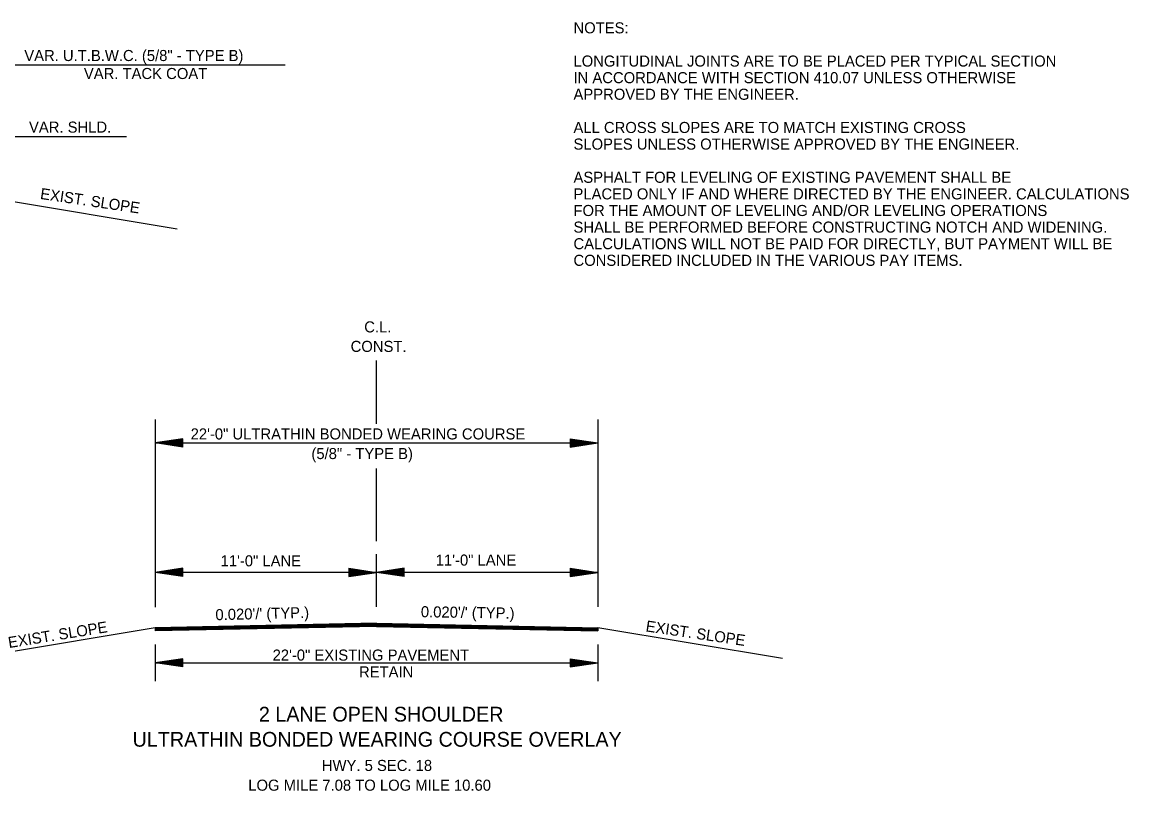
# Model space of a CAD drawing. Extents: x 2263886 to 2266026, y -3122850 to -3121850.
# Drawn here: x 2265457.8 to 2265517.8, y -3122646.9 to -3122605.2 of the extents above; entities that cross this region are included whole.
import ezdxf

# ---------------------------------------------------------------- set-up
doc = ezdxf.new("R2010")
doc.units = 0
doc.layers.add('Default', color=7, linetype='Continuous')
doc.layers.add('R_Border Prem', color=7, linetype='Continuous')

msp = doc.modelspace()

# ---------------------------------------------------------------- linework, layer by layer
at = {"layer": 'R_Border Prem'}
for p, q in [((2265472.094, -3122607.527), (2265448.881, -3122607.527)), ((2265463.497, -3122611.414), (2265452.189, -3122611.414)), ((2265466.233, -3122616.414), (2265456.226, -3122614.746)), ((2265477.045, -3122626.982), (2265477.045, -3122623.539)), ((2265465.045, -3122626.734), (2265465.045, -3122636.907)), ((2265466.545, -3122627.784), (2265465.045, -3122628.009)), ((2265465.045, -3122628.009), (2265489.037, -3122628.009)), ((2265466.545, -3122628.234), (2265465.045, -3122628.009)), ((2265466.545, -3122627.822), (2265465.295, -3122628.009)), ((2265466.545, -3122628.197), (2265465.295, -3122628.009)), ((2265466.545, -3122627.86), (2265465.553, -3122628.009)), ((2265466.545, -3122628.159), (2265465.553, -3122628.009)), ((2265466.545, -3122627.898), (2265465.803, -3122628.009)), ((2265466.545, -3122628.121), (2265465.803, -3122628.009)), ((2265466.545, -3122627.936), (2265466.057, -3122628.009)), ((2265466.545, -3122628.082), (2265466.057, -3122628.009)), ((2265466.545, -3122627.974), (2265466.308, -3122628.009)), ((2265466.545, -3122628.045), (2265466.308, -3122628.009)), ((2265466.545, -3122628.234), (2265466.545, -3122627.784)), ((2265487.537, -3122627.784), (2265489.037, -3122628.009)), ((2265487.537, -3122627.784), (2265487.537, -3122628.234)), ((2265487.537, -3122627.822), (2265488.787, -3122628.009)), ((2265487.537, -3122627.86), (2265488.529, -3122628.009)), ((2265487.537, -3122627.898), (2265488.279, -3122628.009)), ((2265487.537, -3122627.937), (2265488.025, -3122628.009)), ((2265487.537, -3122627.974), (2265487.774, -3122628.009)), ((2265487.537, -3122628.234), (2265489.037, -3122628.009)), ((2265487.537, -3122628.083), (2265488.025, -3122628.009)), ((2265487.537, -3122628.159), (2265488.529, -3122628.009)), ((2265487.537, -3122628.197), (2265488.787, -3122628.009)), ((2265487.537, -3122628.121), (2265488.279, -3122628.009)), ((2265487.537, -3122628.045), (2265487.774, -3122628.009)), ((2265477.045, -3122633.333), (2265477.045, -3122629.398)), ((2265477.045, -3122636.89), (2265477.045, -3122634.035)), ((2265466.545, -3122634.799), (2265465.045, -3122635.024)), ((2265477.045, -3122635.024), (2265465.045, -3122635.024)), ((2265466.545, -3122635.249), (2265465.045, -3122635.024)), ((2265466.545, -3122634.836), (2265465.295, -3122635.024)), ((2265466.545, -3122635.211), (2265465.295, -3122635.024)), ((2265466.545, -3122634.875), (2265465.553, -3122635.024)), ((2265466.545, -3122635.173), (2265465.553, -3122635.024)), ((2265466.545, -3122634.912), (2265465.803, -3122635.024)), ((2265466.545, -3122635.136), (2265465.803, -3122635.024)), ((2265466.545, -3122634.95), (2265466.057, -3122635.024)), ((2265466.545, -3122635.097), (2265466.057, -3122635.024)), ((2265466.545, -3122634.989), (2265466.308, -3122635.024)), ((2265466.545, -3122635.059), (2265466.308, -3122635.024)), ((2265466.545, -3122635.249), (2265466.545, -3122634.799)), ((2265475.545, -3122634.799), (2265477.045, -3122635.024)), ((2265475.545, -3122634.799), (2265475.545, -3122635.249)), ((2265475.545, -3122634.836), (2265476.794, -3122635.024)), ((2265475.545, -3122634.875), (2265476.536, -3122635.024)), ((2265475.545, -3122634.912), (2265476.286, -3122635.024)), ((2265475.545, -3122634.951), (2265476.032, -3122635.024)), ((2265475.545, -3122634.989), (2265475.782, -3122635.024)), ((2265475.545, -3122635.249), (2265477.045, -3122635.024)), ((2265475.545, -3122635.097), (2265476.032, -3122635.024)), ((2265475.545, -3122635.173), (2265476.536, -3122635.024)), ((2265475.545, -3122635.211), (2265476.794, -3122635.024)), ((2265475.545, -3122635.136), (2265476.286, -3122635.024)), ((2265475.545, -3122635.059), (2265475.782, -3122635.024)), ((2265478.545, -3122634.799), (2265477.045, -3122635.024)), ((2265489.037, -3122635.024), (2265477.045, -3122635.024)), ((2265478.545, -3122635.249), (2265477.045, -3122635.024)), ((2265478.545, -3122634.836), (2265477.295, -3122635.024)), ((2265478.545, -3122635.211), (2265477.295, -3122635.024)), ((2265478.545, -3122634.875), (2265477.553, -3122635.024)), ((2265478.545, -3122635.173), (2265477.553, -3122635.024)), ((2265478.545, -3122634.912), (2265477.803, -3122635.024)), ((2265478.545, -3122635.136), (2265477.803, -3122635.024)), ((2265478.545, -3122634.95), (2265478.057, -3122635.024)), ((2265478.545, -3122635.097), (2265478.057, -3122635.024)), ((2265478.545, -3122634.989), (2265478.308, -3122635.024)), ((2265478.545, -3122635.059), (2265478.308, -3122635.024)), ((2265478.545, -3122635.249), (2265478.545, -3122634.799)), ((2265487.537, -3122634.799), (2265489.037, -3122635.024)), ((2265487.537, -3122634.799), (2265487.537, -3122635.249)), ((2265487.537, -3122634.836), (2265488.787, -3122635.024)), ((2265487.537, -3122634.875), (2265488.529, -3122635.024)), ((2265487.537, -3122634.912), (2265488.279, -3122635.024)), ((2265487.537, -3122634.951), (2265488.025, -3122635.024)), ((2265487.537, -3122634.989), (2265487.774, -3122635.024)), ((2265487.537, -3122635.249), (2265489.037, -3122635.024)), ((2265487.537, -3122635.097), (2265488.025, -3122635.024)), ((2265487.537, -3122635.173), (2265488.529, -3122635.024)), ((2265487.537, -3122635.211), (2265488.787, -3122635.024)), ((2265487.537, -3122635.136), (2265488.279, -3122635.024)), ((2265487.537, -3122635.059), (2265487.774, -3122635.024)), ((2265465.045, -3122638.024), (2265455.038, -3122639.692)), ((2265477.045, -3122637.784), (2265465.045, -3122638.024)), ((2265477.045, -3122637.814), (2265465.045, -3122638.054)), ((2265465.045, -3122638.024), (2265465.048, -3122638.194)), ((2265477.046, -3122637.844), (2265465.046, -3122638.084)), ((2265477.046, -3122637.874), (2265465.046, -3122638.114)), ((2265477.047, -3122637.904), (2265465.047, -3122638.144)), ((2265477.048, -3122637.934), (2265465.048, -3122638.174)), ((2265477.048, -3122637.954), (2265465.048, -3122638.194)), ((2265477.041, -3122637.954), (2265489.041, -3122638.194)), ((2265477.042, -3122637.904), (2265489.042, -3122638.144)), ((2265477.042, -3122637.934), (2265489.042, -3122638.174)), ((2265477.043, -3122637.844), (2265489.043, -3122638.084)), ((2265477.043, -3122637.874), (2265489.043, -3122638.114)), ((2265477.044, -3122637.814), (2265489.044, -3122638.054)), ((2265477.045, -3122637.784), (2265489.045, -3122638.024)), ((2265489.045, -3122638.024), (2265489.041, -3122638.194)), ((2265499.051, -3122639.692), (2265489.045, -3122638.024)), ((2265465.045, -3122638.926), (2265465.045, -3122640.926)), ((2265489.037, -3122638.926), (2265489.037, -3122640.926)), ((2265466.545, -3122639.701), (2265465.045, -3122639.926)), ((2265465.045, -3122639.926), (2265489.037, -3122639.926)), ((2265466.545, -3122640.151), (2265465.045, -3122639.926)), ((2265466.545, -3122639.738), (2265465.295, -3122639.926)), ((2265466.545, -3122640.113), (2265465.295, -3122639.926)), ((2265466.545, -3122639.777), (2265465.553, -3122639.926)), ((2265466.545, -3122640.075), (2265465.553, -3122639.926)), ((2265466.545, -3122639.814), (2265465.803, -3122639.926)), ((2265466.545, -3122640.038), (2265465.803, -3122639.926)), ((2265466.545, -3122639.852), (2265466.057, -3122639.926)), ((2265466.545, -3122639.999), (2265466.057, -3122639.926)), ((2265466.545, -3122639.891), (2265466.308, -3122639.926)), ((2265466.545, -3122639.961), (2265466.308, -3122639.926)), ((2265466.545, -3122640.151), (2265466.545, -3122639.701)), ((2265487.537, -3122639.701), (2265489.037, -3122639.926)), ((2265487.537, -3122639.701), (2265487.537, -3122640.151)), ((2265487.537, -3122639.738), (2265488.787, -3122639.926)), ((2265487.537, -3122639.777), (2265488.529, -3122639.926)), ((2265487.537, -3122639.814), (2265488.279, -3122639.926)), ((2265487.537, -3122639.853), (2265488.025, -3122639.926)), ((2265487.537, -3122639.891), (2265487.774, -3122639.926)), ((2265487.537, -3122640.151), (2265489.037, -3122639.926)), ((2265487.537, -3122639.999), (2265488.025, -3122639.926)), ((2265487.537, -3122640.075), (2265488.529, -3122639.926)), ((2265487.537, -3122640.113), (2265488.787, -3122639.926)), ((2265487.537, -3122640.038), (2265488.279, -3122639.926)), ((2265487.537, -3122639.961), (2265487.774, -3122639.926))]:
    msp.add_line(p, q, dxfattribs=at)
msp.add_lwpolyline([(2265489.037, -3122626.734), (2265489.037, -3122636.89)], dxfattribs=at)

# ---------------------------------------------------------------- texts
at = {"layer": 'Default'}
for s, p in [('22\'-0" EXISTING PAVEMENT', (2265471.411, -3122639.806)), ('RETAIN', (2265476.093, -3122640.716))]:
    msp.add_text(s, height=0.6, dxfattribs=at).set_placement(p)
at = {"layer": 'R_Border Prem'}
for s, height, p in [('NOTES: ', 0.6, (2265487.717, -3122605.81)), ('VAR. U.T.B.W.C. (5/8" - TYPE B)', 0.6, (2265457.953, -3122607.31)), ('LONGITUDINAL JOINTS ARE TO BE PLACED PER TYPICAL SECTION', 0.6, (2265487.717, -3122607.61)), ('VAR. TACK COAT', 0.6, (2265461.182, -3122608.285)), ('IN ACCORDANCE WITH SECTION 410.07 UNLESS OTHERWISE', 0.6, (2265487.717, -3122608.51)), ('APPROVED BY THE ENGINEER.', 0.6, (2265487.717, -3122609.41)), ('VAR. SHLD.', 0.6, (2265458.207, -3122611.191)), ('ALL CROSS SLOPES ARE TO MATCH EXISTING CROSS ', 0.6, (2265487.717, -3122611.21)), ('SLOPES UNLESS OTHERWISE APPROVED BY THE ENGINEER.', 0.6, (2265487.717, -3122612.11)), ('ASPHALT FOR LEVELING OF EXISTING PAVEMENT SHALL BE', 0.6, (2265487.717, -3122613.91)), ('PLACED ONLY IF AND WHERE DIRECTED BY THE ENGINEER. CALCULATIONS', 0.6, (2265487.717, -3122614.81)), ('FOR THE AMOUNT OF LEVELING AND/OR LEVELING OPERATIONS', 0.6, (2265487.717, -3122615.71)), ('SHALL BE PERFORMED BEFORE CONSTRUCTING NOTCH AND WIDENING.', 0.6, (2265487.717, -3122616.61)), ('CALCULATIONS WILL NOT BE PAID FOR DIRECTLY, BUT PAYMENT WILL BE ', 0.6, (2265487.717, -3122617.51)), ('CONSIDERED INCLUDED IN THE VARIOUS PAY ITEMS.', 0.6, (2265487.717, -3122618.41)), ('C.L.', 0.6, (2265476.377, -3122622.019)), ('CONST.', 0.6, (2265475.64, -3122623.075)), ('22\'-0" ULTRATHIN BONDED WEARING COURSE', 0.6, (2265466.968, -3122627.82)), ('(5/8" - TYPE B)', 0.6, (2265473.514, -3122628.884)), ('11\'-0" LANE', 0.6, (2265468.592, -3122634.698)), ('11\'-0" LANE', 0.6, (2265480.251, -3122634.658)), ('2 LANE OPEN SHOULDER ', 0.8, (2265470.666, -3122643.11)), ('ULTRATHIN BONDED WEARING COURSE OVERLAY', 0.8, (2265463.822, -3122644.472)), ('HWY. 5 SEC. 18', 0.6, (2265474.081, -3122645.788)), ('LOG MILE 7.08 TO LOG MILE 10.60', 0.6, (2265470.092, -3122646.858))]:
    msp.add_text(s, height=height, dxfattribs=at).set_placement(p)
for s, rotation, p in [('EXIST. SLOPE', 351.57554, (2265458.787, -3122614.78)), ("0.020'/' (TYP.)", 1.42536, (2265468.319, -3122637.619)), ("0.020'/' (TYP.)", 359.06285, (2265479.442, -3122637.452)), ('EXIST. SLOPE', 9.15344, (2265457.125, -3122639.129)), ('EXIST. SLOPE', 351.57554, (2265491.605, -3122638.219))]:
    msp.add_text(s, height=0.6, rotation=rotation, dxfattribs=at).set_placement(p)

doc.saveas('drawing.dxf')
